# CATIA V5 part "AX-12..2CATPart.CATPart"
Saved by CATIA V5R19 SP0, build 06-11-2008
Part number: DX124_DUMMY
Revision: 27
Definition: design
Nomenclature: DX124_DUMMY
Source: made
Description: NOT SPECIFIED
Bounding box of the stored display mesh (mm): x -16 to 16, y -38.5 to 11.5, z -19 to 19
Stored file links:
  G:\project guitar elect\AX-12..2CATPart.CATPart
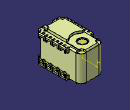
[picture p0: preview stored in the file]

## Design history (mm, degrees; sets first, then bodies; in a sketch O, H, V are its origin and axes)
Set1
  DatumSurface1 "CURVE_BOUNDED_SURFACE #7207"
  DatumSurface2 "CURVE_BOUNDED_SURFACE #7250"
  DatumSurface3 "CURVE_BOUNDED_SURFACE #7292"
  DatumSurface4 "CURVE_BOUNDED_SURFACE #7334"
  DatumSurface5 "CURVE_BOUNDED_SURFACE #7375"
  DatumSurface6 "CURVE_BOUNDED_SURFACE #7451"
  DatumSurface7 "CURVE_BOUNDED_SURFACE #7526"
  DatumSurface8 "CURVE_BOUNDED_SURFACE #7737"
  DatumSurface9 "CURVE_BOUNDED_SURFACE #7833"
  DatumSurface10 "CURVE_BOUNDED_SURFACE #7875"
  DatumSurface11 "CURVE_BOUNDED_SURFACE #7970"
  DatumSurface12 "CURVE_BOUNDED_SURFACE #8046"
  DatumSurface13 "CURVE_BOUNDED_SURFACE #8088"
  DatumSurface14 "CURVE_BOUNDED_SURFACE #8129"
  DatumSurface15 "CURVE_BOUNDED_SURFACE #8204"
  DatumSurface16 "CURVE_BOUNDED_SURFACE #8245"
  DatumSurface17 "CURVE_BOUNDED_SURFACE #8286"
  DatumSurface18 "CURVE_BOUNDED_SURFACE #8361"
  DatumSurface19 "CURVE_BOUNDED_SURFACE #9345"
  DatumSurface20 "CURVE_BOUNDED_SURFACE #9397"
  DatumSurface21 "CURVE_BOUNDED_SURFACE #9488"
  DatumSurface22 "CURVE_BOUNDED_SURFACE #9579"
  DatumSurface23 "CURVE_BOUNDED_SURFACE #9670"
  DatumSurface24 "CURVE_BOUNDED_SURFACE #9761"
  DatumSurface25 "CURVE_BOUNDED_SURFACE #9851"
  DatumSurface26 "CURVE_BOUNDED_SURFACE #9929"
  DatumSurface27 "CURVE_BOUNDED_SURFACE #10008"
  DatumSurface28 "CURVE_BOUNDED_SURFACE #10058"
  DatumSurface29 "CURVE_BOUNDED_SURFACE #10131"
  DatumSurface30 "CURVE_BOUNDED_SURFACE #10210"
  DatumSurface31 "CURVE_BOUNDED_SURFACE #10289"
  DatumSurface32 "CURVE_BOUNDED_SURFACE #10368"
  DatumSurface33 "CURVE_BOUNDED_SURFACE #10429"
  DatumSurface34 "CURVE_BOUNDED_SURFACE #10500"
  DatumSurface35 "CURVE_BOUNDED_SURFACE #10573"
  DatumSurface36 "CURVE_BOUNDED_SURFACE #10652"
  DatumSurface37 "CURVE_BOUNDED_SURFACE #10731"
  DatumSurface38 "CURVE_BOUNDED_SURFACE #10810"
  DatumSurface39 "CURVE_BOUNDED_SURFACE #10871"
  DatumSurface40 "CURVE_BOUNDED_SURFACE #10943"
  DatumSurface41 "CURVE_BOUNDED_SURFACE #10985"
  DatumSurface42 "CURVE_BOUNDED_SURFACE #11027"
  DatumSurface43 "CURVE_BOUNDED_SURFACE #11077"
  DatumSurface44 "CURVE_BOUNDED_SURFACE #11153"
  DatumSurface45 "CURVE_BOUNDED_SURFACE #11230"
  DatumSurface46 "CURVE_BOUNDED_SURFACE #11307"
  DatumSurface47 "CURVE_BOUNDED_SURFACE #11384"
  DatumSurface48 "CURVE_BOUNDED_SURFACE #11460"
  DatumSurface49 "CURVE_BOUNDED_SURFACE #11958"
  DatumSurface50 "CURVE_BOUNDED_SURFACE #12121"
  DatumSurface51 "CURVE_BOUNDED_SURFACE #12250"
  DatumSurface52 "CURVE_BOUNDED_SURFACE #12382"
  DatumSurface53 "CURVE_BOUNDED_SURFACE #12492"
  DatumSurface54 "CURVE_BOUNDED_SURFACE #12532"
  DatumSurface55 "CURVE_BOUNDED_SURFACE #12571"
  DatumSurface56 "CURVE_BOUNDED_SURFACE #12683"
  DatumSurface57 "CURVE_BOUNDED_SURFACE #12743"
  DatumSurface58 "CURVE_BOUNDED_SURFACE #12800"
  DatumSurface59 "CURVE_BOUNDED_SURFACE #12871"
  DatumSurface60 "CURVE_BOUNDED_SURFACE #12949"
  DatumSurface61 "CURVE_BOUNDED_SURFACE #13027"
  DatumSurface62 "CURVE_BOUNDED_SURFACE #13105"
  DatumSurface63 "CURVE_BOUNDED_SURFACE #13165"
  DatumSurface64 "CURVE_BOUNDED_SURFACE #13236"
  DatumSurface65 "CURVE_BOUNDED_SURFACE #13309"
  DatumSurface66 "CURVE_BOUNDED_SURFACE #13388"
  DatumSurface67 "CURVE_BOUNDED_SURFACE #13467"
  DatumSurface68 "CURVE_BOUNDED_SURFACE #13546"
  DatumSurface69 "CURVE_BOUNDED_SURFACE #13607"
  DatumSurface70 "CURVE_BOUNDED_SURFACE #13679"
  DatumSurface71 "CURVE_BOUNDED_SURFACE #13721"
  DatumSurface72 "CURVE_BOUNDED_SURFACE #13761"
  DatumSurface73 "CURVE_BOUNDED_SURFACE #13812"
  DatumSurface74 "CURVE_BOUNDED_SURFACE #13888"
  DatumSurface75 "CURVE_BOUNDED_SURFACE #13965"
  DatumSurface76 "CURVE_BOUNDED_SURFACE #14042"
  DatumSurface77 "CURVE_BOUNDED_SURFACE #14119"
  DatumSurface78 "CURVE_BOUNDED_SURFACE #14208"
  DatumSurface79 "CURVE_BOUNDED_SURFACE #14298"
  DatumSurface80 "CURVE_BOUNDED_SURFACE #14388"
  DatumSurface81 "CURVE_BOUNDED_SURFACE #14478"
  DatumSurface82 "CURVE_BOUNDED_SURFACE #14568"
  DatumSurface83 "CURVE_BOUNDED_SURFACE #14617"
  DatumSurface84 "CURVE_BOUNDED_SURFACE #14690"
  DatumSurface85 "CURVE_BOUNDED_SURFACE #14765"
  DatumSurface86 "CURVE_BOUNDED_SURFACE #14840"
  DatumSurface87 "CURVE_BOUNDED_SURFACE #14915"
  DatumSurface88 "CURVE_BOUNDED_SURFACE #14989"
  DatumSurface89 "CURVE_BOUNDED_SURFACE #15029"
  DatumSurface90 "CURVE_BOUNDED_SURFACE #15068"
  DatumSurface91 "CURVE_BOUNDED_SURFACE #15118"
  DatumSurface92 "CURVE_BOUNDED_SURFACE #15170"
  DatumSurface93 "CURVE_BOUNDED_SURFACE #15199"
  DatumSurface94 "CURVE_BOUNDED_SURFACE #15229"
  DatumSurface95 "CURVE_BOUNDED_SURFACE #15259"
  DatumSurface96 "CURVE_BOUNDED_SURFACE #15289"
  DatumSurface97 "CURVE_BOUNDED_SURFACE #15320"
  DatumSurface98 "CURVE_BOUNDED_SURFACE #15369"
  DatumSurface99 "CURVE_BOUNDED_SURFACE #15421"
  DatumSurface100 "CURVE_BOUNDED_SURFACE #15471"
  DatumSurface101 "CURVE_BOUNDED_SURFACE #16436"
  DatumSurface102 "CURVE_BOUNDED_SURFACE #16487"
  DatumSurface103 "CURVE_BOUNDED_SURFACE #16536"
  DatumSurface104 "CURVE_BOUNDED_SURFACE #16585"
  DatumSurface105 "CURVE_BOUNDED_SURFACE #16636"
  DatumSurface106 "CURVE_BOUNDED_SURFACE #16685"
  DatumSurface107 "CURVE_BOUNDED_SURFACE #16734"
  DatumSurface108 "CURVE_BOUNDED_SURFACE #16783"
  DatumSurface109 "CURVE_BOUNDED_SURFACE #16834"
  DatumSurface110 "CURVE_BOUNDED_SURFACE #16887"
  DatumSurface111 "CURVE_BOUNDED_SURFACE #16940"
  DatumSurface112 "CURVE_BOUNDED_SURFACE #16992"
  DatumSurface113 "CURVE_BOUNDED_SURFACE #17083"
  DatumSurface114 "CURVE_BOUNDED_SURFACE #17174"
  DatumSurface115 "CURVE_BOUNDED_SURFACE #17265"
  DatumSurface116 "CURVE_BOUNDED_SURFACE #17355"
  DatumSurface117 "CURVE_BOUNDED_SURFACE #17446"
  DatumSurface118 "CURVE_BOUNDED_SURFACE #17522"
  DatumSurface119 "CURVE_BOUNDED_SURFACE #17598"
  DatumSurface120 "CURVE_BOUNDED_SURFACE #17674"
  DatumSurface121 "CURVE_BOUNDED_SURFACE #17750"
  DatumSurface122 "CURVE_BOUNDED_SURFACE #17799"
  DatumSurface123 "CURVE_BOUNDED_SURFACE #17840"
  DatumSurface124 "CURVE_BOUNDED_SURFACE #17915"
  DatumSurface125 "CURVE_BOUNDED_SURFACE #17992"
  DatumSurface126 "CURVE_BOUNDED_SURFACE #18069"
  DatumSurface127 "CURVE_BOUNDED_SURFACE #18146"
  DatumSurface128 "CURVE_BOUNDED_SURFACE #18221"
  DatumSurface129 "CURVE_BOUNDED_SURFACE #18714"
  DatumSurface130 "CURVE_BOUNDED_SURFACE #18789"
  DatumSurface131 "CURVE_BOUNDED_SURFACE #18864"
  DatumSurface132 "CURVE_BOUNDED_SURFACE #18939"
  DatumSurface133 "CURVE_BOUNDED_SURFACE #19014"
  DatumSurface134 "CURVE_BOUNDED_SURFACE #19089"
  DatumSurface135 "CURVE_BOUNDED_SURFACE #19139"
  DatumSurface136 "CURVE_BOUNDED_SURFACE #19215"
  DatumSurface137 "CURVE_BOUNDED_SURFACE #19292"
  DatumSurface138 "CURVE_BOUNDED_SURFACE #19369"
  DatumSurface139 "CURVE_BOUNDED_SURFACE #19446"
  DatumSurface140 "CURVE_BOUNDED_SURFACE #19536"
  DatumSurface141 "CURVE_BOUNDED_SURFACE #19625"
  DatumSurface142 "CURVE_BOUNDED_SURFACE #19715"
  DatumSurface143 "CURVE_BOUNDED_SURFACE #19805"
  DatumSurface144 "CURVE_BOUNDED_SURFACE #19895"
  DatumSurface145 "CURVE_BOUNDED_SURFACE #19943"
  DatumSurface146 "CURVE_BOUNDED_SURFACE #19983"
  DatumSurface147 "CURVE_BOUNDED_SURFACE #20023"
  DatumSurface148 "CURVE_BOUNDED_SURFACE #20128"
  DatumSurface149 "CURVE_BOUNDED_SURFACE #20168"
  DatumSurface150 "CURVE_BOUNDED_SURFACE #20208"
  DatumSurface151 "CURVE_BOUNDED_SURFACE #20256"
  DatumSurface152 "CURVE_BOUNDED_SURFACE #20330"
  DatumSurface153 "CURVE_BOUNDED_SURFACE #20404"
  DatumSurface154 "CURVE_BOUNDED_SURFACE #20444"
  DatumSurface155 "CURVE_BOUNDED_SURFACE #20502"
  DatumSurface156 "CURVE_BOUNDED_SURFACE #20559"
  DatumSurface157 "CURVE_BOUNDED_SURFACE #20598"
  DatumSurface158 "CURVE_BOUNDED_SURFACE #20639"
  DatumSurface159 "CURVE_BOUNDED_SURFACE #20680"
  DatumSurface160 "CURVE_BOUNDED_SURFACE #20730"
  DatumSurface161 "CURVE_BOUNDED_SURFACE #20769"
  DatumSurface162 "CURVE_BOUNDED_SURFACE #20819"
  DatumSurface163 "CURVE_BOUNDED_SURFACE #20858"
  DatumSurface164 "CURVE_BOUNDED_SURFACE #20906"
  DatumSurface165 "CURVE_BOUNDED_SURFACE #20946"
  DatumSurface166 "CURVE_BOUNDED_SURFACE #20985"
  DatumSurface167 "CURVE_BOUNDED_SURFACE #21043"
  DatumSurface168 "CURVE_BOUNDED_SURFACE #21101"
  DatumSurface169 "CURVE_BOUNDED_SURFACE #21153"
  DatumSurface170 "CURVE_BOUNDED_SURFACE #21311"
  DatumSurface171 "CURVE_BOUNDED_SURFACE #21352"
  DatumSurface172 "CURVE_BOUNDED_SURFACE #21394"
  DatumSurface173 "CURVE_BOUNDED_SURFACE #21435"
  DatumSurface174 "CURVE_BOUNDED_SURFACE #21486"
  DatumSurface175 "CURVE_BOUNDED_SURFACE #21542"
  DatumSurface176 "CURVE_BOUNDED_SURFACE #21599"
  DatumSurface177 "CURVE_BOUNDED_SURFACE #21639"
  DatumSurface178 "CURVE_BOUNDED_SURFACE #21696"
  DatumSurface179 "CURVE_BOUNDED_SURFACE #21754"
  DatumSurface180 "CURVE_BOUNDED_SURFACE #21795"
  DatumSurface181 "CURVE_BOUNDED_SURFACE #21852"
  DatumSurface182 "CURVE_BOUNDED_SURFACE #21910"
  DatumSurface183 "CURVE_BOUNDED_SURFACE #21950"
  DatumSurface184 "CURVE_BOUNDED_SURFACE #22007"
  DatumSurface185 "CURVE_BOUNDED_SURFACE #22065"
  DatumSurface186 "CURVE_BOUNDED_SURFACE #22106"
  DatumSurface187 "CURVE_BOUNDED_SURFACE #22163"
  DatumSurface188 "CURVE_BOUNDED_SURFACE #22221"
  DatumSurface189 "CURVE_BOUNDED_SURFACE #22261"
  DatumSurface190 "CURVE_BOUNDED_SURFACE #22318"
  DatumSurface191 "CURVE_BOUNDED_SURFACE #22376"
  DatumSurface192 "CURVE_BOUNDED_SURFACE #22417"
  DatumSurface193 "CURVE_BOUNDED_SURFACE #22474"
  DatumSurface194 "CURVE_BOUNDED_SURFACE #22532"
  DatumSurface195 "CURVE_BOUNDED_SURFACE #22572"
  DatumSurface196 "CURVE_BOUNDED_SURFACE #22630"
  DatumSurface197 "CURVE_BOUNDED_SURFACE #22689"
  DatumSurface198 "CURVE_BOUNDED_SURFACE #22746"
  DatumSurface199 "CURVE_BOUNDED_SURFACE #22804"
  DatumSurface200 "CURVE_BOUNDED_SURFACE #22845"
  DatumSurface201 "CURVE_BOUNDED_SURFACE #22907"
  DatumSurface202 "CURVE_BOUNDED_SURFACE #22955"
  DatumSurface203 "CURVE_BOUNDED_SURFACE #23044"
  DatumSurface204 "CURVE_BOUNDED_SURFACE #23111"
  DatumSurface205 "CURVE_BOUNDED_SURFACE #23158"
  DatumSurface206 "CURVE_BOUNDED_SURFACE #23205"
  DatumSurface207 "CURVE_BOUNDED_SURFACE #23259"
  DatumSurface208 "CURVE_BOUNDED_SURFACE #23314"
  DatumSurface209 "CURVE_BOUNDED_SURFACE #23383"
  DatumSurface210 "CURVE_BOUNDED_SURFACE #23505"
  DatumSurface211 "CURVE_BOUNDED_SURFACE #23547"
  DatumSurface212 "CURVE_BOUNDED_SURFACE #23589"
  DatumSurface213 "CURVE_BOUNDED_SURFACE #23647"
  DatumSurface214 "CURVE_BOUNDED_SURFACE #23827"
  DatumSurface215 "CURVE_BOUNDED_SURFACE #23877"
  DatumSurface216 "CURVE_BOUNDED_SURFACE #23932"
  DatumSurface217 "CURVE_BOUNDED_SURFACE #23980"
  DatumSurface218 "CURVE_BOUNDED_SURFACE #24042"
  DatumSurface219 "CURVE_BOUNDED_SURFACE #24131"
  DatumSurface220 "CURVE_BOUNDED_SURFACE #24179"
  DatumSurface221 "CURVE_BOUNDED_SURFACE #24241"
  DatumSurface222 "CURVE_BOUNDED_SURFACE #24281"
  DatumSurface223 "CURVE_BOUNDED_SURFACE #24322"
  DatumSurface224 "CURVE_BOUNDED_SURFACE #24361"
  DatumSurface225 "CURVE_BOUNDED_SURFACE #24401"
  DatumSurface226 "CURVE_BOUNDED_SURFACE #24462"
  DatumSurface227 "CURVE_BOUNDED_SURFACE #24510"
  DatumSurface228 "CURVE_BOUNDED_SURFACE #24595"
  DatumSurface229 "CURVE_BOUNDED_SURFACE #24660"
  DatumSurface230 "CURVE_BOUNDED_SURFACE #24717"
  DatumSurface231 "CURVE_BOUNDED_SURFACE #24765"
  DatumSurface232 "CURVE_BOUNDED_SURFACE #24849"
  DatumSurface233 "CURVE_BOUNDED_SURFACE #24897"
  DatumSurface234 "CURVE_BOUNDED_SURFACE #24959"
  DatumSurface235 "CURVE_BOUNDED_SURFACE #24999"
  DatumSurface236 "CURVE_BOUNDED_SURFACE #25038"
  DatumSurface237 "CURVE_BOUNDED_SURFACE #25077"
  DatumSurface238 "CURVE_BOUNDED_SURFACE #25131"
  DatumSurface239 "CURVE_BOUNDED_SURFACE #25179"
  DatumSurface240 "CURVE_BOUNDED_SURFACE #25241"
  DatumSurface241 "CURVE_BOUNDED_SURFACE #25296"
  DatumSurface242 "CURVE_BOUNDED_SURFACE #25343"
  DatumSurface243 "CURVE_BOUNDED_SURFACE #27073"
  DatumSurface244 "CURVE_BOUNDED_SURFACE #27139"
  DatumSurface245 "CURVE_BOUNDED_SURFACE #27179"
  DatumSurface246 "CURVE_BOUNDED_SURFACE #27244"
  DatumSurface247 "CURVE_BOUNDED_SURFACE #27284"
  DatumSurface248 "CURVE_BOUNDED_SURFACE #27343"
  DatumSurface249 "CURVE_BOUNDED_SURFACE #27400"
  DatumSurface250 "CURVE_BOUNDED_SURFACE #27441"
  DatumSurface251 "CURVE_BOUNDED_SURFACE #27499"
  DatumSurface252 "CURVE_BOUNDED_SURFACE #27557"
  DatumSurface253 "CURVE_BOUNDED_SURFACE #27598"
  DatumSurface254 "CURVE_BOUNDED_SURFACE #27656"
  DatumSurface255 "CURVE_BOUNDED_SURFACE #27714"
  DatumSurface256 "CURVE_BOUNDED_SURFACE #27755"
  DatumSurface257 "CURVE_BOUNDED_SURFACE #27813"
  DatumSurface258 "CURVE_BOUNDED_SURFACE #27871"
  DatumSurface259 "CURVE_BOUNDED_SURFACE #27912"
  DatumSurface260 "CURVE_BOUNDED_SURFACE #27970"
  DatumSurface261 "CURVE_BOUNDED_SURFACE #28028"
  DatumSurface262 "CURVE_BOUNDED_SURFACE #28069"
  DatumSurface263 "CURVE_BOUNDED_SURFACE #28127"
  DatumSurface264 "CURVE_BOUNDED_SURFACE #28185"
  DatumSurface265 "CURVE_BOUNDED_SURFACE #28226"
  DatumSurface266 "CURVE_BOUNDED_SURFACE #28284"
  DatumSurface267 "CURVE_BOUNDED_SURFACE #28342"
  DatumSurface268 "CURVE_BOUNDED_SURFACE #28393"
  DatumSurface269 "CURVE_BOUNDED_SURFACE #28433"
  DatumSurface270 "CURVE_BOUNDED_SURFACE #28472"
  DatumSurface271 "CURVE_BOUNDED_SURFACE #28513"
  DatumSurface272 "CURVE_BOUNDED_SURFACE #28563"
  DatumSurface273 "CURVE_BOUNDED_SURFACE #28602"
  DatumSurface274 "CURVE_BOUNDED_SURFACE #28674"
  DatumSurface275 "CURVE_BOUNDED_SURFACE #28747"
  DatumSurface276 "CURVE_BOUNDED_SURFACE #28820"
  DatumSurface277 "CURVE_BOUNDED_SURFACE #28894"
  DatumSurface278 "CURVE_BOUNDED_SURFACE #28942"
  DatumSurface279 "CURVE_BOUNDED_SURFACE #28982"
  DatumSurface280 "CURVE_BOUNDED_SURFACE #29021"
  DatumSurface281 "CURVE_BOUNDED_SURFACE #29069"
  DatumSurface282 "CURVE_BOUNDED_SURFACE #29109"
  DatumSurface283 "CURVE_BOUNDED_SURFACE #29149"
  DatumSurface284 "CURVE_BOUNDED_SURFACE #29196"
  DatumSurface285 "CURVE_BOUNDED_SURFACE #29244"
  DatumSurface286 "CURVE_BOUNDED_SURFACE #29284"
  DatumSurface287 "CURVE_BOUNDED_SURFACE #29324"
  DatumSurface288 "CURVE_BOUNDED_SURFACE #29371"
  DatumSurface289 "CURVE_BOUNDED_SURFACE #29419"
  DatumSurface290 "CURVE_BOUNDED_SURFACE #29459"
  DatumSurface291 "CURVE_BOUNDED_SURFACE #29499"
  DatumSurface292 "CURVE_BOUNDED_SURFACE #29546"
  DatumSurface293 "CURVE_BOUNDED_SURFACE #29585"
  DatumSurface294 "CURVE_BOUNDED_SURFACE #29624"
  DatumSurface295 "CURVE_BOUNDED_SURFACE #29663"
  DatumSurface296 "CURVE_BOUNDED_SURFACE #29703"
  DatumSurface297 "CURVE_BOUNDED_SURFACE #29742"
  DatumSurface298 "CURVE_BOUNDED_SURFACE #29781"
  DatumSurface299 "CURVE_BOUNDED_SURFACE #29820"
  DatumSurface300 "CURVE_BOUNDED_SURFACE #29860"
  DatumSurface301 "CURVE_BOUNDED_SURFACE #29899"
  DatumSurface302 "CURVE_BOUNDED_SURFACE #29938"
  DatumSurface303 "CURVE_BOUNDED_SURFACE #29977"
  DatumSurface304 "CURVE_BOUNDED_SURFACE #30017"
  DatumSurface305 "CURVE_BOUNDED_SURFACE #30056"
  DatumSurface306 "CURVE_BOUNDED_SURFACE #30095"
  DatumSurface307 "CURVE_BOUNDED_SURFACE #30134"
  DatumSurface308 "CURVE_BOUNDED_SURFACE #30174"
  DatumSurface309 "CURVE_BOUNDED_SURFACE #30213"
  DatumSurface310 "CURVE_BOUNDED_SURFACE #30252"
  DatumSurface311 "CURVE_BOUNDED_SURFACE #30291"
  DatumSurface312 "CURVE_BOUNDED_SURFACE #30331"
  DatumSurface313 "CURVE_BOUNDED_SURFACE #30370"
  DatumSurface314 "CURVE_BOUNDED_SURFACE #30409"
  DatumSurface315 "CURVE_BOUNDED_SURFACE #30448"
  DatumSurface316 "CURVE_BOUNDED_SURFACE #30488"
  DatumSurface317 "CURVE_BOUNDED_SURFACE #30527"
  DatumSurface318 "CURVE_BOUNDED_SURFACE #30566"
  DatumSurface319 "CURVE_BOUNDED_SURFACE #30615"
  DatumSurface320 "CURVE_BOUNDED_SURFACE #30654"
  DatumSurface321 "CURVE_BOUNDED_SURFACE #30705"
  DatumSurface322 "CURVE_BOUNDED_SURFACE #30745"
  DatumSurface323 "CURVE_BOUNDED_SURFACE #30785"
  DatumSurface324 "CURVE_BOUNDED_SURFACE #30824"
  DatumSurface325 "CURVE_BOUNDED_SURFACE #30863"
  DatumSurface326 "CURVE_BOUNDED_SURFACE #30903"
  DatumSurface327 "CURVE_BOUNDED_SURFACE #30960"
  DatumSurface328 "CURVE_BOUNDED_SURFACE #31016"
  DatumSurface329 "CURVE_BOUNDED_SURFACE #31055"
  DatumSurface330 "CURVE_BOUNDED_SURFACE #31094"
  DatumSurface331 "CURVE_BOUNDED_SURFACE #31133"
  DatumSurface332 "CURVE_BOUNDED_SURFACE #31181"
  DatumSurface333 "CURVE_BOUNDED_SURFACE #31221"
  DatumSurface334 "CURVE_BOUNDED_SURFACE #31260"
  DatumSurface335 "CURVE_BOUNDED_SURFACE #31308"
  DatumSurface336 "CURVE_BOUNDED_SURFACE #31348"
  DatumSurface337 "CURVE_BOUNDED_SURFACE #31388"
  DatumSurface338 "CURVE_BOUNDED_SURFACE #31435"
  DatumSurface339 "CURVE_BOUNDED_SURFACE #31483"
  DatumSurface340 "CURVE_BOUNDED_SURFACE #31523"
  DatumSurface341 "CURVE_BOUNDED_SURFACE #31563"
  DatumSurface342 "CURVE_BOUNDED_SURFACE #31610"
  DatumSurface343 "CURVE_BOUNDED_SURFACE #31658"
  DatumSurface344 "CURVE_BOUNDED_SURFACE #31698"
  DatumSurface345 "CURVE_BOUNDED_SURFACE #31738"
  DatumSurface346 "CURVE_BOUNDED_SURFACE #31785"
  DatumSurface347 "CURVE_BOUNDED_SURFACE #31836"
  DatumSurface348 "CURVE_BOUNDED_SURFACE #31886"
  DatumSurface349 "CURVE_BOUNDED_SURFACE #31935"
  DatumSurface350 "CURVE_BOUNDED_SURFACE #31965"
  DatumSurface351 "CURVE_BOUNDED_SURFACE #31995"
  DatumSurface352 "CURVE_BOUNDED_SURFACE #32025"
  DatumSurface353 "CURVE_BOUNDED_SURFACE #32054"
  DatumSurface354 "CURVE_BOUNDED_SURFACE #32085"
  DatumSurface355 "CURVE_BOUNDED_SURFACE #32134"
  DatumSurface356 "CURVE_BOUNDED_SURFACE #32185"
  DatumSurface357 "CURVE_BOUNDED_SURFACE #32234"
  DatumSurface358 "CURVE_BOUNDED_SURFACE #32283"
  DatumSurface359 "CURVE_BOUNDED_SURFACE #32334"
  DatumSurface360 "CURVE_BOUNDED_SURFACE #32383"
  DatumSurface361 "CURVE_BOUNDED_SURFACE #32432"
  DatumSurface362 "CURVE_BOUNDED_SURFACE #32483"
  DatumSurface363 "CURVE_BOUNDED_SURFACE #32532"
  DatumSurface364 "CURVE_BOUNDED_SURFACE #32585"
  DatumSurface365 "CURVE_BOUNDED_SURFACE #32640"
  DatumSurface366 "CURVE_BOUNDED_SURFACE #32689"
  DatumSurface367 "CURVE_BOUNDED_SURFACE #32739"
  DatumSurface368 "CURVE_BOUNDED_SURFACE #32788"
  DatumSurface369 "CURVE_BOUNDED_SURFACE #32818"
  DatumSurface370 "CURVE_BOUNDED_SURFACE #32848"
  DatumSurface371 "CURVE_BOUNDED_SURFACE #32878"
  DatumSurface372 "CURVE_BOUNDED_SURFACE #32907"
  DatumSurface373 "CURVE_BOUNDED_SURFACE #32938"
  DatumSurface374 "CURVE_BOUNDED_SURFACE #32987"
  DatumSurface375 "CURVE_BOUNDED_SURFACE #33038"
  DatumSurface376 "CURVE_BOUNDED_SURFACE #33087"
  DatumSurface377 "CURVE_BOUNDED_SURFACE #33136"
  DatumSurface378 "CURVE_BOUNDED_SURFACE #33187"
  DatumSurface379 "CURVE_BOUNDED_SURFACE #33236"
  DatumSurface380 "CURVE_BOUNDED_SURFACE #33285"
  DatumSurface381 "CURVE_BOUNDED_SURFACE #33336"
  DatumSurface382 "CURVE_BOUNDED_SURFACE #33385"
  DatumSurface383 "CURVE_BOUNDED_SURFACE #33438"
  DatumSurface384 "CURVE_BOUNDED_SURFACE #33493"
  DatumSurface385 "CURVE_BOUNDED_SURFACE #33542"
  DatumSurface386 "CURVE_BOUNDED_SURFACE #33582"
  DatumSurface387 "CURVE_BOUNDED_SURFACE #33629"
  DatumSurface388 "CURVE_BOUNDED_SURFACE #33677"
  DatumSurface389 "CURVE_BOUNDED_SURFACE #33717"
  DatumSurface390 "CURVE_BOUNDED_SURFACE #33757"
  DatumSurface391 "CURVE_BOUNDED_SURFACE #33804"
  DatumSurface392 "CURVE_BOUNDED_SURFACE #33852"
  DatumSurface393 "CURVE_BOUNDED_SURFACE #33892"
  DatumSurface394 "CURVE_BOUNDED_SURFACE #33932"
  DatumSurface395 "CURVE_BOUNDED_SURFACE #33979"
  DatumSurface396 "CURVE_BOUNDED_SURFACE #34027"
  DatumSurface397 "CURVE_BOUNDED_SURFACE #34067"
  DatumSurface398 "CURVE_BOUNDED_SURFACE #34107"
  DatumSurface399 "CURVE_BOUNDED_SURFACE #34154"
  DatumSurface400 "CURVE_BOUNDED_SURFACE #34202"
  DatumSurface401 "CURVE_BOUNDED_SURFACE #34242"
  DatumSurface402 "CURVE_BOUNDED_SURFACE #34282"
  DatumSurface403 "CURVE_BOUNDED_SURFACE #34329"
  DatumSurface404 "CURVE_BOUNDED_SURFACE #34377"
  DatumSurface405 "CURVE_BOUNDED_SURFACE #34417"
  DatumSurface406 "CURVE_BOUNDED_SURFACE #34457"
  DatumSurface407 "CURVE_BOUNDED_SURFACE #34504"
  DatumSurface408 "CURVE_BOUNDED_SURFACE #34552"
  DatumSurface409 "CURVE_BOUNDED_SURFACE #34592"
  DatumSurface410 "CURVE_BOUNDED_SURFACE #34632"
  DatumSurface411 "CURVE_BOUNDED_SURFACE #34679"
  DatumSurface412 "CURVE_BOUNDED_SURFACE #34733"
  DatumSurface413 "CURVE_BOUNDED_SURFACE #34788"
  DatumSurface414 "CURVE_BOUNDED_SURFACE #34818"
  DatumSurface415 "CURVE_BOUNDED_SURFACE #34848"
  DatumSurface416 "CURVE_BOUNDED_SURFACE #34878"
  DatumSurface417 "CURVE_BOUNDED_SURFACE #34908"
  DatumSurface418 "CURVE_BOUNDED_SURFACE #34938"
  DatumSurface419 "CURVE_BOUNDED_SURFACE #34987"
  DatumSurface420 "CURVE_BOUNDED_SURFACE #35038"
  DatumSurface421 "CURVE_BOUNDED_SURFACE #35087"
  DatumSurface422 "CURVE_BOUNDED_SURFACE #35136"
  DatumSurface423 "CURVE_BOUNDED_SURFACE #35187"
  DatumSurface424 "CURVE_BOUNDED_SURFACE #35236"
  DatumSurface425 "CURVE_BOUNDED_SURFACE #35285"
  DatumSurface426 "CURVE_BOUNDED_SURFACE #35336"
  DatumSurface427 "CURVE_BOUNDED_SURFACE #35385"
  DatumSurface428 "CURVE_BOUNDED_SURFACE #35434"
  DatumSurface429 "CURVE_BOUNDED_SURFACE #35483"
  DatumSurface430 "CURVE_BOUNDED_SURFACE #35532"
  DatumSurface431 "CURVE_BOUNDED_SURFACE #35587"
  DatumSurface432 "CURVE_BOUNDED_SURFACE #35627"
  DatumSurface433 "CURVE_BOUNDED_SURFACE #35675"
  DatumSurface434 "CURVE_BOUNDED_SURFACE #35750"
  DatumSurface435 "CURVE_BOUNDED_SURFACE #35799"
  DatumSurface436 "CURVE_BOUNDED_SURFACE #35847"
  DatumSurface437 "CURVE_BOUNDED_SURFACE #35921"
  DatumSurface438 "CURVE_BOUNDED_SURFACE #36011"
  DatumSurface439 "CURVE_BOUNDED_SURFACE #36051"
  DatumSurface440 "CURVE_BOUNDED_SURFACE #36091"
  DatumSurface441 "CURVE_BOUNDED_SURFACE #36131"
  DatumSurface442 "CURVE_BOUNDED_SURFACE #36170"
  DatumSurface443 "CURVE_BOUNDED_SURFACE #36211"
  DatumSurface444 "CURVE_BOUNDED_SURFACE #36258"
  DatumSurface445 "CURVE_BOUNDED_SURFACE #36344"
  DatumSurface446 "CURVE_BOUNDED_SURFACE #36444"
  DatumSurface447 "CURVE_BOUNDED_SURFACE #36496"
  DatumSurface448 "CURVE_BOUNDED_SURFACE #36546"
  DatumSurface449 "CURVE_BOUNDED_SURFACE #36829"
  DatumSurface450 "CURVE_BOUNDED_SURFACE #36884"
  DatumSurface451 "CURVE_BOUNDED_SURFACE #36923"
  DatumSurface452 "CURVE_BOUNDED_SURFACE #36997"
  DatumSurface453 "CURVE_BOUNDED_SURFACE #37037"
  DatumSurface454 "CURVE_BOUNDED_SURFACE #37077"
  DatumSurface455 "CURVE_BOUNDED_SURFACE #37117"
  DatumSurface456 "CURVE_BOUNDED_SURFACE #37157"
  DatumSurface457 "CURVE_BOUNDED_SURFACE #37196"
  DatumSurface458 "CURVE_BOUNDED_SURFACE #37235"
  DatumSurface459 "CURVE_BOUNDED_SURFACE #37274"
  Sketch1 on yz-plane, origin (0, 0, 0), H (0, 1, 0), V (0, 0, 1)
    axis line L1 (0, 28.822) -> (0, -24.9828)
    point P1 (0, 28.822)
    coincidence: P1 V
    vertical: L1 V
Body1 (main body)
  Sketch2 on DatumSurface214, origin (0, 0, 16.6), H (1, 0, 0), V (0, 1, 0)
    circle A1 centre (0, 0) radius 4.5
    reference projected arc E1 centre (0, 0) radius 4.5 from (4.5, 0) to (-4.5, 0) ccw from edge of DatumSurface214
    circle A2 centre (0, 0) radius 5.3852
    distance A1 E1 = 0
  Pad1: profile Sketch2, direction (0, 0, -1), length 1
